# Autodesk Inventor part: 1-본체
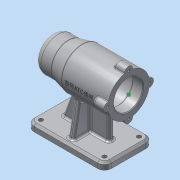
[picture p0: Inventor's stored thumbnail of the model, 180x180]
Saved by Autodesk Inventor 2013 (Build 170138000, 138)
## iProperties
Created: 2019-07
Part Number: 1-본체
Material: 알루미늄 6061
Document SubType Name: Modeling
Designer: Administrator
Density: 2.71 g/cm^3
Mass: 646.782 g
Surface Area: 655.584 cm^2
Volume: 238.665 cm^3
Author: Administrator
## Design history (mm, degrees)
sketch "스케치1"
  geometry: L1 (0, 0)-(-112, 0); L2 (0, 0)-(0, 30); L3 (0, 30)-(-67, 30); L4 (-67, 30)-(-87, 25); L5 (-87, 25)-(-112, 25); L6 (-112, 25)-(-112, 0)
  constraints: 12 end point, 3 perpendicular, 1 horizontal, 1 parallel
  dimensions: "d0" = 112 distance of L1.start L1.end; "d1" = 60 diameter of L3 L1; "d2" = 50 diameter of L5 L1; "d3" = 25 distance of L4.end L5.end; "d4" = 45 distance from line of L3.end L6
revolve "회전1" sketch "스케치1" stored, may be unused: angle "d5" = 90 deg
sketch "스케치3"
  geometry: C1 r 30 at (0, 0) reference; C2 r 21 at (0, 0)
  constraints: 1 centre point, 1 coincident
  dimensions: "d7" = 42 diameter of C2
extrude "돌출1" cut sketch "스케치3" distance "d9" = 15; taper "d10" = 0 deg
sketch "스케치4"
  geometry: C1 r 21 at (0, 0) reference; C2 r 24 at (0, 0)
  constraints: 1 centre point, 1 coincident
  dimensions: "d11" = 48 diameter of C2
extrude "돌출2" cut sketch "스케치4" distance "d13" = 54; taper "d14" = 0 deg
sketch "스케치5"
  geometry: C1 r 24 at (0, 0) reference; C2 r 21 at (0, 0)
  constraints: 1 centre point, 1 coincident
  dimensions: "d15" = 42 diameter of C2
extrude "돌출3" cut sketch "스케치5" distance "d17" = 12; taper "d18" = 0 deg
sketch "스케치6"
  geometry: C1 r 21 at (0, 0) reference; C2 r 17.5 at (0, 0)
  constraints: 1 centre point, 1 coincident
  dimensions: "d19" = 35 diameter of C2
extrude "돌출4" cut sketch "스케치6" distance "d21" = 18; taper "d22" = 0 deg
sketch "스케치7"
  geometry: C1 r 17.5 at (0, 0) reference; C2 r 16 at (0, 0)
  constraints: 1 centre point, 1 coincident
  dimensions: "d23" = 32 diameter of C2
extrude "돌출5" cut sketch "스케치7" distance "d25" = 4; taper "d26" = 0 deg
sketch "스케치8"
  geometry: C1 r 16 at (0, 0) reference; C2 r 10.5 at (0, 0)
  constraints: 1 centre point, 1 coincident
  dimensions: "d27" = 21 diameter of C2
extrude "돌출6" cut sketch "스케치8" distance "d29" = 3; taper "d30" = 0 deg
sketch "스케치9"
  geometry: 1 further point
node "작업 평면1"
sketch "스케치10"
  geometry: L1 (0, 35)-(112, 35); L2 (112, 35)-(112, -35); L3 (112, -35)-(0, -35); L4 (0, -35)-(0, 35); 2 further points
  constraints: 8 end point, 2 parallel, 1 coincident, 1 horizontal, 1 midpoint, 1 perpendicular
  dimensions: "d32" = 112 distance of L1.start L1.end; "d34" = 70 distance of L1.end L2.end
extrude "돌출7" join sketch "스케치10" distance "d35" = 10; taper "d36" = 0 deg
node "작업 평면2"
sketch "스케치11"
  geometry: L1 (-10, 70)-(-10, 0) reference; L2 (0, 0)-(-10, 0) reference; L3 (0, 70)-(-10, 70) reference; L4 (-10, 7)-(-57.334, 15.346); L5 (-57.334, 54.654)-(-10, 63); A1 r 30 centre (-80, 35) between (-57.334, 15.346) and (-57.334, 54.654) reference; 1 further point
  constraints: 4 end point, 2 point on circle, 2 point on line, 1 equal length
  dimensions: "d37" = 7 distance of L4.start L1.end; "d38" = 100 deg angle of L4 L1; "d39" = 7 distance of L5.end L1.start
extrude "돌출8" join sketch "스케치11" stored distance "d40" = 8; taper "d41" = 0 deg
sketch "스케치12"
  geometry: L1 (87, -25)-(67, -30) reference; L2 (112, -25)-(87, -25) reference; L3 (67, -30)-(0, -30) reference; L4 (60, -22.666)-(60, -70) reference; L5 (0, -70)-(112, -70) reference; L6 (112, -80)-(112, -70) reference; L7 (92, -70)-(76.57, -27.607); 1 further point
  constraints: 2 end point, 2 point on line
  dimensions: "d42" = 20 distance of L7.start L5.end; "d43" = 110 deg angle of L7 L5
feature "리브1" sketch "스케치12" dims "d44" = 1, "d45" = 8, "d46" = 0, "d47" = 0, "d48" = 1, "d49" = 1
sketch "스케치13"
  geometry: L1 (52, -30)-(0, -30) reference; L2 (52, -70)-(52, -22.666) reference; L3 (0, -70)-(112, -70) reference; L4 (25, -70)-(25, -30); 1 further point
  constraints: 2 end point, 2 point on line, 1 perpendicular
  dimensions: "d50" = 25 distance of L3.start L4.start
feature "리브2" sketch "스케치13" dims "d51" = 1, "d52" = 8, "d53" = 0, "d54" = 0, "d55" = 1, "d56" = 1
sketch "스케치14"
  geometry: L1 (-112, 35)-(-112, -35) reference; L2 (-112, -35)-(0, -35) reference; L3 (0, 35)-(-112, 35) reference; L4 (0, 0)-(-112, 0); L5 (-56, 35)-(-56, -35); C1 r 3 at (-102, 25)
  constraints: 4 end point, 3 midpoint, 1 centre point
  dimensions: "d57" = 6 diameter of C1; "d59" = 25 distance from line of L4 C1.centre; "d60" = 46 distance from line of L5 C1.centre
extrude "돌출9" cut sketch "스케치14" stored distance "d61" = 8; taper "d62" = 0 deg
sketch "스케치15"
  geometry: A1 r 30 centre (0, 0) between (-30, 0) and (-29.4, -5.97) reference; A2 r 6 centre (-30, 0) between (-29.4, 5.97) and (-29.4, -5.97)
  constraints: 5 point on circle, 1 centre point, 1 horizontal alignment
  dimensions: "d69" = 12 diameter of A2
extrude "돌출10" join sketch "스케치15" distance "d71" = 16; taper "d72" = 0 deg
sketch "스케치16"
  geometry: A1 r 6 centre (0, 0) between (0.6, 5.97) and (0.6, -5.97) reference; 1 further point
  constraints: 1 coincident
hole "구멍1" sketch "스케치16" at (0, 0) diameter "d76" = 3.242; stored, may be unused: countersink angle "d80" = 90 deg, drill point angle "d82" = 118 deg; dims "d77" = 8, "d78" = 4, "d79" = 2, "d81" = 11
node "작업 평면3"
sketch "스케치17"
  geometry: 2 further points
  constraints: 1 horizontal alignment, 1 other
  dimensions: "d87" = 42 distance of point (-42, 0) point (0, 0)
feature "엠보싱1" sketch "스케치17" dims "d88" = 0.5, "d89" = 0
fillet "모깎기1" dims "d90" = 10
fillet "모깎기2" dims "d91" = 10
fillet "모깎기14" dims "d103" = 3
fillet "모깎기15" dims "d104" = 3
fillet "모깎기16" dims "d105" = 3
chamfer "모따기1" distance "d106" = 3; stored, may be unused: second distance "d107" = 2, angle "d108" = 45 deg
chamfer "모따기2" distance "d109" = 1; stored, may be unused: second distance "d110" = 2, angle "d111" = 45 deg
fillet "모깎기17" dims "d112" = 3
fillet "모깎기20" dims "d115" = 0.3
fillet "모깎기23" dims "d118" = 0.3
fillet "모깎기24" dims "d119" = 0.3
fillet "모깎기25" dims "d120" = 3
fillet "모깎기26" dims "d121" = 3
fillet "모깎기27" dims "d122" = 3
fillet "모깎기28" dims "d123" = 1
node "솔리드1"
pattern_linear "직사각형 패턴1" dims "d65" = 92
pattern_circular "원형 패턴1" dims angle "d74" = 360 deg
pattern_circular "원형 패턴2" dims angle "d84" = 360 deg
